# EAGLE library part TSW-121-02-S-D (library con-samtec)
THROUGH-HOLE .025" SQ POST HEADER Source: Samtec TSW.pdf
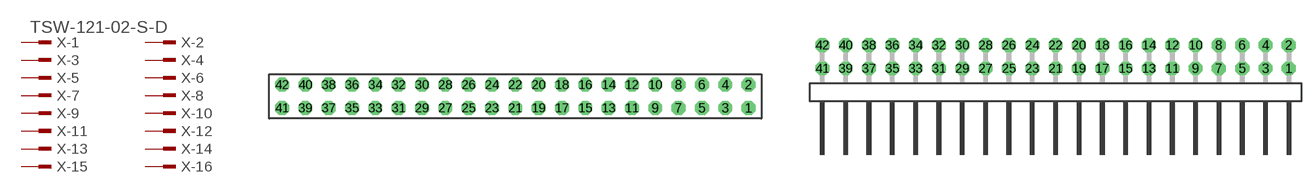
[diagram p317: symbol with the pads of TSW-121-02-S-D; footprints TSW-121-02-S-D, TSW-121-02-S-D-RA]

Designator prefix X; gates -1=MPINV -2=MPIN -3=MPIN -4=MPIN -5=MPIN -6=MPIN -7=MPIN -8=MPIN -9=MPIN -10=MPIN -11=MPIN -12=MPIN -13=MPIN -14=MPIN -15=MPIN -16=MPIN -17=MPIN -18=MPIN -19=MPIN -20=MPIN -21=MPIN -22=MPIN -23=MPIN -24=MPIN -25=MPIN -26=MPIN -27=MPIN -28=MPIN -29=MPIN -30=MPIN -31=MPIN -32=MPIN -33=MPIN -34=MPIN -35=MPIN -36=MPIN -37=MPIN -38=MPIN -39=MPIN -40=MPIN -41=MPIN -42=MPIN

## TSW-121-02-S-D (OC_FARNELL: unknown; OC_NEWARK: unknown)  [TSW-121-02-S-D]
1  -1:1  pas
2  -2:1  pas
3  -3:1  pas
4  -4:1  pas
5  -5:1  pas
6  -6:1  pas
7  -7:1  pas
8  -8:1  pas
9  -9:1  pas
10  -10:1  pas
11  -11:1  pas
12  -12:1  pas
13  -13:1  pas
14  -14:1  pas
15  -15:1  pas
16  -16:1  pas
17  -17:1  pas
18  -18:1  pas
19  -19:1  pas
20  -20:1  pas
21  -21:1  pas
22  -22:1  pas
23  -23:1  pas
24  -24:1  pas
25  -25:1  pas
26  -26:1  pas
27  -27:1  pas
28  -28:1  pas
29  -29:1  pas
30  -30:1  pas
31  -31:1  pas
32  -32:1  pas
33  -33:1  pas
34  -34:1  pas
35  -35:1  pas
36  -36:1  pas
37  -37:1  pas
38  -38:1  pas
39  -39:1  pas
40  -40:1  pas
41  -41:1  pas
42  -42:1  pas

## TSW-121-02-S-D-RA (OC_FARNELL: unknown; OC_NEWARK: unknown)  [TSW-121-02-S-D-RA]
Pads as for TSW-121-02-S-D

## Footprint TSW-121-02-S-D (pad centres in mm)
THROUGH-HOLE .025" SQ POST HEADER Source: Samtec TSW.pdf
drill 1 pad 1.5 octagon: 1 25.4,-1.27; 2 25.4,1.27; 3 22.86,-1.27; 4 22.86,1.27; 5 20.32,-1.27; 6 20.32,1.27; 7 17.78,-1.27; 8 17.78,1.27; 9 15.24,-1.27; 10 15.24,1.27; 11 12.7,-1.27; 12 12.7,1.27; 13 10.16,-1.27; 14 10.16,1.27; 15 7.62,-1.27; 16 7.62,1.27; 17 5.08,-1.27; 18 5.08,1.27; 19 2.54,-1.27; 20 2.54,1.27; 21 0,-1.27; 22 0,1.27; 23 -2.54,-1.27; 24 -2.54,1.27; 25 -5.08,-1.27; 26 -5.08,1.27; 27 -7.62,-1.27; 28 -7.62,1.27; 29 -10.16,-1.27; 30 -10.16,1.27; 31 -12.7,-1.27; 32 -12.7,1.27; 33 -15.24,-1.27; 34 -15.24,1.27; 35 -17.78,-1.27; 36 -17.78,1.27; 37 -20.32,-1.27; 38 -20.32,1.27; 39 -22.86,-1.27; 40 -22.86,1.27; 41 -25.4,-1.27; 42 -25.4,1.27

## Footprint TSW-121-02-S-D-RA (pad centres in mm)
THROUGH-HOLE .025" SQ POST HEADER Source: Samtec TSW.pdf
drill 1 pad 1.5 octagon: 1 25.4,1.524; 2 25.4,4.064; 3 22.86,1.524; 4 22.86,4.064; 5 20.32,1.524; 6 20.32,4.064; 7 17.78,1.524; 8 17.78,4.064; 9 15.24,1.524; 10 15.24,4.064; 11 12.7,1.524; 12 12.7,4.064; 13 10.16,1.524; 14 10.16,4.064; 15 7.62,1.524; 16 7.62,4.064; 17 5.08,1.524; 18 5.08,4.064; 19 2.54,1.524; 20 2.54,4.064; 21 0,1.524; 22 0,4.064; 23 -2.54,1.524; 24 -2.54,4.064; 25 -5.08,1.524; 26 -5.08,4.064; 27 -7.62,1.524; 28 -7.62,4.064; 29 -10.16,1.524; 30 -10.16,4.064; 31 -12.7,1.524; 32 -12.7,4.064; 33 -15.24,1.524; 34 -15.24,4.064; 35 -17.78,1.524; 36 -17.78,4.064; 37 -20.32,1.524; 38 -20.32,4.064; 39 -22.86,1.524; 40 -22.86,4.064; 41 -25.4,1.524; 42 -25.4,4.064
